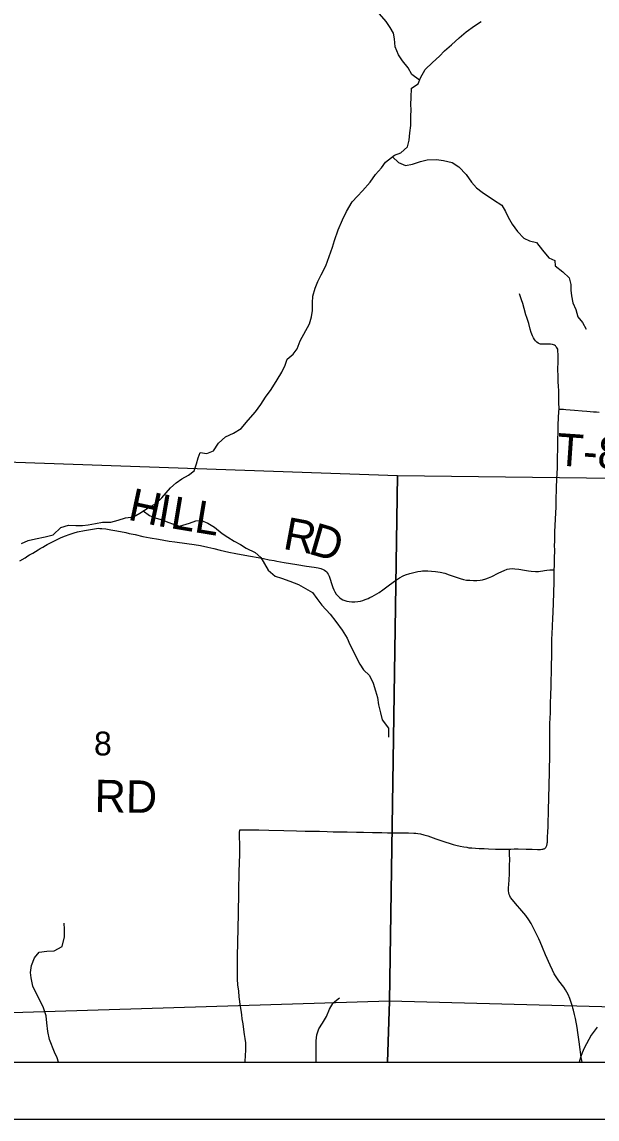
# Model space of a CAD drawing. Extents: x -14196 to 143, y -6096 to 28.
# Drawn here: x 59.582 to 60.591, y 16.799 to 18.723 of the extents above; entities that cross this region are included whole.
import ezdxf

# ---------------------------------------------------------------- set-up
doc = ezdxf.new("R2010")
doc.units = 0
for name, color, linetype in [('GM_X_Corporation', 7, 'Continuous'), ('GM_X_Minor_River', 7, 'Continuous'), ('GM_X_Section_Text', 7, 'Continuous'), ('GM_X_Township_Road', 7, 'Continuous'), ('GM_X_Township_Road_Text', 7, 'Continuous'), ('GM_X_Unincorporated', 7, 'Continuous'), ('SH_Data', 7, 'Continuous')]:
    doc.layers.add(name, color=color, linetype=linetype)

msp = doc.modelspace()

# ---------------------------------------------------------------- linework, layer by layer
at = {"layer": 'GM_X_Corporation'}
for points in [[(60.8954, 18.8061), (59.8722, 18.8218), (59.855, 18.8221), (59.6927, 18.8245), (59.1965, 18.8421), (58.9182, 18.8487), (58.1028, 18.8711), (58.1028, 16.8985), (64.9028, 16.8985)], [(60.8954, 18.8061), (59.8722, 18.8218), (59.855, 18.8221), (59.6927, 18.8245), (59.1965, 18.8421), (58.9182, 18.8487), (58.1028, 18.8711), (58.1028, 16.8985), (62.3117, 16.8985)]]:
    msp.add_lwpolyline(points, dxfattribs=at)
for points in [[(60.2411, 17.9277), (60.2268, 17.0055), (59.2619, 16.9758), (59.1861, 17.9645)], [(61.3312, 17.9144), (61.3, 16.9769), (60.2268, 17.0055), (60.2411, 17.9277)], [(59.2592, 16.8985), (60.2234, 16.8985), (60.2268, 17.0055), (59.2619, 16.9758)], [(60.2234, 16.8985), (61.2982, 16.8985), (61.3, 16.9769), (60.2268, 17.0055)]]:
    msp.add_lwpolyline(points, close=True, dxfattribs=at)
at = {"layer": 'GM_X_Minor_River'}
for points in [[(60.2795, 18.6211), (60.266, 18.6314), (60.2599, 18.6427), (60.2496, 18.6551), (60.2427, 18.6657), (60.2369, 18.6797), (60.2356, 18.6941), (60.234, 18.704), (60.2283, 18.7138), (60.221, 18.7243), (60.2095, 18.7379), (60.2038, 18.7477), (60.1991, 18.7598), (60.1941, 18.7704), (60.1887, 18.7837), (60.1724, 18.8073)], [(59.8531, 17.9148), (59.8629, 17.9217), (59.8745, 17.9282), (59.8843, 17.9359), (59.8884, 17.948), (59.8913, 17.9587), (59.8947, 17.9682), (59.9068, 17.9664), (59.9181, 17.971), (59.9271, 17.9843), (59.9391, 17.9954), (59.9535, 18.002), (59.9666, 18.0104), (59.979, 18.0245), (59.9918, 18.0394), (60.0011, 18.052), (60.0098, 18.0649), (60.0195, 18.0787), (60.03, 18.0954), (60.0382, 18.1091), (60.0438, 18.1213), (60.0478, 18.1316), (60.058, 18.1404), (60.0651, 18.1499), (60.0703, 18.1639), (60.0867, 18.1936), (60.09, 18.2062), (60.0918, 18.2172), (60.0921, 18.2305), (60.0924, 18.2422), (60.0964, 18.2563), (60.1016, 18.2681), (60.1072, 18.2795), (60.1154, 18.2958), (60.1213, 18.3118), (60.1273, 18.3285), (60.1306, 18.3403), (60.1372, 18.3589), (60.1447, 18.3764), (60.1514, 18.3909), (60.1615, 18.4076), (60.1708, 18.4176), (60.1795, 18.4271), (60.193, 18.4424), (60.2023, 18.4557), (60.2129, 18.4676), (60.2203, 18.4775), (60.2358, 18.4897), (60.2471, 18.494), (60.2587, 18.5043), (60.2617, 18.5161), (60.2627, 18.529), (60.2645, 18.5419), (60.2647, 18.5582), (60.265, 18.5692), (60.2646, 18.5787), (60.2649, 18.5908), (60.2655, 18.6075), (60.2772, 18.6151), (60.2812, 18.6254), (60.2895, 18.6399), (60.3026, 18.6521), (60.3146, 18.6632), (60.3233, 18.6727), (60.3357, 18.6835), (60.3492, 18.6957), (60.3616, 18.7064), (60.3763, 18.7167), (60.388, 18.724)], [(60.2322, 18.4869), (60.2427, 18.4769), (60.2549, 18.4716), (60.2673, 18.474), (60.2813, 18.4787), (60.2934, 18.4814), (60.3097, 18.4823), (60.3218, 18.4805), (60.337, 18.4768), (60.3488, 18.4693), (60.3614, 18.4557), (60.371, 18.4425), (60.3797, 18.4327), (60.3897, 18.4248), (60.4095, 18.4113), (60.4239, 18.402), (60.4304, 18.391), (60.4355, 18.3808), (60.4424, 18.3687), (60.4516, 18.3559), (60.463, 18.3442), (60.4729, 18.3394), (60.4847, 18.3364), (60.4954, 18.3232), (60.5068, 18.3097), (60.5171, 18.3052), (60.5179, 18.2957), (60.5309, 18.2848), (60.542, 18.2747), (60.5451, 18.2626), (60.5452, 18.2531), (60.5464, 18.2429), (60.5488, 18.2307), (60.5542, 18.219), (60.5573, 18.2058), (60.5657, 18.196), (60.5722, 18.1847)], [(59.5813, 17.8081), (59.5934, 17.8139), (59.6062, 17.8166), (59.6228, 17.8198), (59.6372, 17.8237), (59.6504, 17.8367), (59.664, 17.8406), (59.6768, 17.8399), (59.6886, 17.84), (59.6984, 17.8412), (59.7113, 17.8432), (59.7237, 17.846), (59.7381, 17.8457), (59.751, 17.8492), (59.7638, 17.8535), (59.7782, 17.8551), (59.7891, 17.8616), (59.8053, 17.8724), (59.8163, 17.8777), (59.8275, 17.8884), (59.8429, 17.906), (59.8531, 17.9148)], [(59.7951, 17.8656), (59.8062, 17.8576), (59.818, 17.8531), (59.8282, 17.8498), (59.8385, 17.8461), (59.848, 17.8424), (59.8586, 17.839), (59.876, 17.8441), (59.8873, 17.8484), (59.8972, 17.8488), (59.9086, 17.8443), (59.92, 17.8369), (59.9337, 17.826), (59.9432, 17.8196), (59.9546, 17.8125), (59.9657, 17.8065), (59.9759, 17.8001), (59.9912, 17.7927), (60.0015, 17.7837), (60.0141, 17.7614), (60.0267, 17.7509), (60.0374, 17.7476), (60.0522, 17.7424), (60.0674, 17.7364), (60.0795, 17.7293), (60.0921, 17.7222), (60.0997, 17.712), (60.1086, 17.7004), (60.1227, 17.6842), (60.133, 17.6717), (60.1438, 17.6563), (60.153, 17.6423), (60.1576, 17.6314), (60.1753, 17.5967), (60.1814, 17.5865), (60.1921, 17.5767), (60.1983, 17.5635), (60.2026, 17.5499), (60.2061, 17.5382), (60.2077, 17.5253), (60.2112, 17.511), (60.214, 17.4992), (60.2251, 17.4846), (60.2252, 17.4687)], [(59.6465, 16.8985), (59.6441, 16.9062), (59.6394, 16.916), (59.6309, 16.9382), (59.6278, 16.9522), (59.6258, 16.9673), (59.6245, 16.9794), (59.6202, 16.9934), (59.6141, 17.0062), (59.6068, 17.0205), (59.6014, 17.0319), (59.5982, 17.0462), (59.5974, 17.0557), (59.5992, 17.0682), (59.6044, 17.0815), (59.6122, 17.0914), (59.6262, 17.093), (59.6387, 17.0938), (59.6527, 17.1015), (59.6571, 17.1182), (59.6569, 17.1318), (59.6565, 17.1424)], [(60.0983, 16.8985), (60.0985, 16.9085), (60.0983, 16.9358), (60.0997, 16.9464), (60.1034, 16.9566), (60.1094, 16.9665), (60.1165, 16.9783), (60.1216, 16.9912), (60.1284, 17.0026), (60.1393, 17.0114)]]:
    msp.add_lwpolyline(points, dxfattribs=at)
at = {"layer": 'GM_X_Township_Road'}
for points in [[(60.5246, 18.0443), (60.5247, 18.0479), (60.5244, 18.0522), (60.5242, 18.0559), (60.5241, 18.0608), (60.5241, 18.0683), (60.524, 18.0768), (60.5236, 18.0838), (60.5232, 18.0924), (60.5228, 18.0997), (60.5227, 18.1047), (60.5225, 18.111), (60.5226, 18.1176), (60.5227, 18.1239), (60.5229, 18.14), (60.5225, 18.1457), (60.5225, 18.1471), (60.5221, 18.1491), (60.5212, 18.1512), (60.5202, 18.153), (60.5191, 18.1542), (60.5182, 18.1552), (60.5165, 18.1564), (60.5147, 18.1572), (60.5128, 18.1577), (60.5098, 18.158), (60.5068, 18.1582), (60.5033, 18.1582), (60.5, 18.1582), (60.4959, 18.158), (60.4933, 18.1582), (60.4918, 18.1584), (60.4903, 18.1589), (60.4881, 18.16), (60.4856, 18.1618), (60.4833, 18.1639), (60.4814, 18.1664), (60.4797, 18.1691), (60.4779, 18.1729), (60.4756, 18.1787), (60.4739, 18.1847), (60.4713, 18.1943), (60.4679, 18.2049), (60.4665, 18.2097), (60.4633, 18.2206), (60.4607, 18.2294), (60.4588, 18.2359), (60.4551, 18.2462)], [(60.5161, 17.7622), (60.5163, 17.7698), (60.5166, 17.7821), (60.5169, 17.7964), (60.5168, 17.805), (60.517, 17.8125), (60.5174, 17.8288), (60.5183, 17.8511), (60.5193, 17.8727), (60.5196, 17.8821), (60.5203, 17.9076), (60.5211, 17.9323), (60.5216, 17.9401), (60.5217, 17.9432), (60.5218, 17.9507), (60.522, 17.9607), (60.5221, 17.9733), (60.5223, 17.9875), (60.5228, 18.007), (60.5232, 18.0177), (60.5236, 18.0276), (60.5237, 18.0329), (60.5239, 18.0361), (60.5243, 18.04), (60.5246, 18.0443)], [(60.5246, 18.0443), (60.5298, 18.044), (60.5325, 18.0438), (60.5362, 18.0435), (60.5518, 18.0421), (60.5652, 18.041), (60.5735, 18.0405), (60.5849, 18.0396), (60.5904, 18.0392), (60.5951, 18.0389)], [(59.5788, 17.778), (59.5878, 17.7835), (59.5924, 17.7865), (59.5957, 17.7883), (59.6013, 17.7917), (59.6058, 17.7944), (59.6106, 17.7972), (59.6143, 17.7994), (59.6187, 17.8018), (59.6235, 17.8046), (59.6267, 17.8065), (59.6361, 17.8114), (59.6452, 17.816), (59.651, 17.8188), (59.6584, 17.8218), (59.6653, 17.8241), (59.6738, 17.827), (59.6798, 17.8286), (59.6922, 17.8311), (59.7023, 17.8331), (59.7097, 17.8344), (59.7129, 17.8348), (59.7158, 17.835), (59.7188, 17.8349), (59.7226, 17.8348), (59.7293, 17.834), (59.7384, 17.8324), (59.7487, 17.8307), (59.7645, 17.8275), (59.7702, 17.8262), (59.7809, 17.8239), (59.7946, 17.8209), (59.8072, 17.8182), (59.8219, 17.8157), (59.8406, 17.8124), (59.8503, 17.8111), (59.8713, 17.8082), (59.8844, 17.8064), (59.8956, 17.8047), (59.9082, 17.8021), (59.9189, 17.7997), (59.9299, 17.7966), (59.9455, 17.7933), (59.9577, 17.7908), (59.973, 17.7882), (59.9832, 17.7864), (59.9967, 17.7836), (60.0062, 17.7818), (60.016, 17.7798), (60.0248, 17.7783), (60.0293, 17.7776), (60.0424, 17.7751), (60.0647, 17.7714), (60.0815, 17.7687), (60.0948, 17.7668), (60.102, 17.7655), (60.1067, 17.7643), (60.1107, 17.7628), (60.1133, 17.7615), (60.1155, 17.7601), (60.1169, 17.7587), (60.118, 17.7572), (60.1197, 17.7546), (60.1213, 17.7512), (60.1226, 17.7478), (60.1258, 17.7365), (60.1277, 17.7312), (60.1293, 17.7273), (60.1313, 17.7235), (60.1337, 17.7197), (60.1362, 17.7164), (60.1394, 17.7134), (60.1423, 17.7113), (60.1452, 17.7098), (60.149, 17.7083), (60.1525, 17.7074), (60.1564, 17.7065), (60.1611, 17.706), (60.1662, 17.7061), (60.1715, 17.7067), (60.1762, 17.7073), (60.1803, 17.7085), (60.1846, 17.71), (60.1895, 17.7121), (60.1923, 17.7134), (60.1966, 17.7154), (60.2007, 17.7177), (60.2087, 17.7226), (60.2155, 17.7271), (60.2272, 17.7358), (60.2374, 17.7432), (60.2448, 17.748), (60.2509, 17.7514), (60.2553, 17.7532), (60.2627, 17.7557), (60.2696, 17.7577), (60.2766, 17.7591), (60.2818, 17.7599), (60.2852, 17.7603), (60.2888, 17.7605), (60.2945, 17.7605), (60.301, 17.7599), (60.3078, 17.7593), (60.3157, 17.7582), (60.3243, 17.7561), (60.3318, 17.7536), (60.3442, 17.7494), (60.3511, 17.7469), (60.3571, 17.7452), (60.3623, 17.7442), (60.368, 17.7439), (60.3742, 17.7436), (60.38, 17.7436), (60.3861, 17.7442), (60.3905, 17.7449), (60.396, 17.7464), (60.401, 17.7481), (60.4066, 17.7505), (60.418, 17.7563), (60.424, 17.7592), (60.4281, 17.7612), (60.4333, 17.7631), (60.4374, 17.764), (60.4424, 17.7645), (60.4472, 17.7642), (60.4538, 17.7635), (60.4641, 17.7615), (60.471, 17.7605), (60.4754, 17.7598), (60.4832, 17.7592), (60.4886, 17.7594), (60.4922, 17.7597), (60.4959, 17.7603), (60.4992, 17.7611), (60.5028, 17.7617), (60.5084, 17.7621), (60.5161, 17.7622)], [(60.4375, 17.2722), (60.4398, 17.2723), (60.4459, 17.2726), (60.4527, 17.2726), (60.467, 17.2723), (60.4773, 17.272), (60.4867, 17.2717), (60.4917, 17.2717), (60.4945, 17.2719), (60.496, 17.2721), (60.497, 17.2724), (60.4982, 17.2728), (60.4993, 17.2734), (60.5002, 17.2741), (60.5012, 17.275), (60.502, 17.2762), (60.5025, 17.2773), (60.5029, 17.2786), (60.5036, 17.2813), (60.5039, 17.2828), (60.504, 17.2842), (60.5041, 17.2856), (60.5044, 17.2914), (60.5049, 17.304), (60.5052, 17.3097), (60.5052, 17.3154), (60.5053, 17.3209), (60.5058, 17.3344), (60.5059, 17.3401), (60.5065, 17.3625), (60.507, 17.383), (60.5077, 17.4083), (60.5078, 17.4114), (60.5081, 17.4353), (60.5082, 17.4425), (60.5082, 17.4494), (60.5081, 17.4589), (60.5081, 17.4614), (60.5081, 17.4676), (60.5082, 17.4719), (60.5082, 17.4738), (60.5083, 17.4781), (60.5084, 17.4831), (60.5086, 17.4861), (60.5085, 17.4905), (60.5092, 17.5045), (60.5093, 17.5092), (60.5094, 17.5141), (60.5096, 17.5261), (60.5103, 17.5447), (60.5105, 17.5558), (60.5107, 17.5692), (60.511, 17.581), (60.5114, 17.5926), (60.5114, 17.5996), (60.5117, 17.6063), (60.5119, 17.6275), (60.512, 17.641), (60.5124, 17.6491), (60.5137, 17.6772), (60.5142, 17.6875), (60.5149, 17.7042), (60.5155, 17.721), (60.516, 17.7416), (60.516, 17.7492), (60.5159, 17.7591), (60.5161, 17.7622)], [(59.9739, 16.8985), (59.9747, 16.9113), (59.9749, 16.918), (59.9751, 16.923), (59.9751, 16.9271), (59.9748, 16.932), (59.9738, 16.9401), (59.9727, 16.9469), (59.9708, 16.9606), (59.9703, 16.9654), (59.9689, 16.9743), (59.9678, 16.9815), (59.9667, 16.9898), (59.9658, 16.9958), (59.9636, 17.0132), (59.9625, 17.0229), (59.9613, 17.0338), (59.9605, 17.0442), (59.9604, 17.0481), (59.9603, 17.051), (59.9604, 17.0599), (59.9605, 17.073), (59.9607, 17.094), (59.9608, 17.0983), (59.9608, 17.1051), (59.961, 17.1133), (59.9616, 17.1284), (59.9617, 17.1374), (59.962, 17.1548), (59.9623, 17.1672), (59.9625, 17.1877), (59.963, 17.2091), (59.9633, 17.2218), (59.9634, 17.2324), (59.9643, 17.2635), (59.9644, 17.2771), (59.9643, 17.282), (59.9642, 17.2925), (59.9642, 17.3006), (59.9643, 17.3061)], [(59.9643, 17.3061), (59.9722, 17.3061), (59.9765, 17.3061), (59.9877, 17.306), (59.998, 17.3059), (60.0155, 17.3056), (60.0417, 17.3047), (60.0639, 17.3041), (60.079, 17.3038), (60.0913, 17.3038), (60.104, 17.3036), (60.1176, 17.3031), (60.1284, 17.3027), (60.1346, 17.3025), (60.1529, 17.3023), (60.1691, 17.302), (60.1815, 17.3017), (60.1972, 17.3013), (60.2135, 17.3011), (60.2234, 17.301), (60.2375, 17.3008), (60.2604, 17.3008), (60.27, 17.3004), (60.2734, 17.3), (60.2765, 17.2996), (60.2814, 17.2987), (60.2874, 17.2975), (60.2941, 17.2955), (60.3084, 17.29), (60.3153, 17.2876), (60.324, 17.2848), (60.3335, 17.2819), (60.3388, 17.2803), (60.3437, 17.2791), (60.3513, 17.2772), (60.3572, 17.2763), (60.3625, 17.2753), (60.3665, 17.2747), (60.3714, 17.2743), (60.3845, 17.2735), (60.3932, 17.2732), (60.4009, 17.2729), (60.4132, 17.2723), (60.4292, 17.2721), (60.4375, 17.2722)], [(60.5652, 16.8985), (60.5646, 16.9011), (60.5636, 16.9067), (60.5618, 16.9207), (60.56, 16.9339), (60.5577, 16.9503), (60.5563, 16.9592), (60.5533, 16.975), (60.5517, 16.9822), (60.5499, 16.9893), (60.5489, 16.9933), (60.5479, 16.9968), (60.5469, 16.9996), (60.5457, 17.003), (60.5432, 17.01), (60.5404, 17.017), (60.5382, 17.021), (60.5358, 17.0251), (60.5327, 17.0297), (60.5243, 17.0413), (60.5197, 17.0479), (60.5161, 17.0535), (60.5128, 17.0598), (60.5089, 17.0685), (60.5007, 17.0869), (60.4955, 17.0994), (60.4913, 17.1092), (60.4891, 17.115), (60.4788, 17.1357), (60.4755, 17.1419), (60.4716, 17.1481), (60.466, 17.1556), (60.459, 17.1638), (60.4481, 17.1768), (60.4426, 17.1834), (60.4396, 17.1871), (60.4381, 17.19), (60.4372, 17.1924), (60.4365, 17.1954), (60.4361, 17.1992), (60.4359, 17.2036), (60.4368, 17.2174), (60.4374, 17.2292), (60.4377, 17.2435), (60.438, 17.2541), (60.4377, 17.2626), (60.4377, 17.2667), (60.4376, 17.2688), (60.4375, 17.2722)]]:
    msp.add_lwpolyline(points, dxfattribs=at)
at = {"layer": 'GM_X_Unincorporated'}
msp.add_line((60.5598, 16.8985), (60.8301, 16.8985), dxfattribs=at)
msp.add_arc((60.7305, 16.8496), 0.1776, 141.669, 164.0188, dxfattribs=at)
at = {"layer": 'SH_Data'}
for p, q in [((58.1028, 16.8985), (64.9028, 16.8985)), ((58.0028, 16.7985), (65.0028, 16.7985))]:
    msp.add_line(p, q, dxfattribs=at)

# ---------------------------------------------------------------- texts
at = {"layer": 'GM_X_Section_Text'}
msp.add_text('8', height=0.0419, rotation=0, dxfattribs=at).set_placement((59.7087, 17.4365))
at = {"layer": 'GM_X_Township_Road_Text'}
for s, height, rotation, p in [('T-838', 0.05682, 356.0584, (60.519, 17.9456)), ('H', 0.0568, 347.9414, (59.7663, 17.8506)), ('I', 0.0568, 350.2259, (59.8176, 17.8396)), ('L', 0.0568, 350.5743, (59.841, 17.8356)), ('L', 0.0568, 350.5977, (59.8829, 17.8287)), ('R', 0.0568, 349.4372, (60.0385, 17.7993)), ('D', 0.0568, 343.7624, (60.0829, 17.7911)), ('RD', 0.05682, 359.0136, (59.7093, 17.3372))]:
    msp.add_text(s, height=height, rotation=rotation, dxfattribs=at).set_placement(p)

doc.saveas('drawing.dxf')
